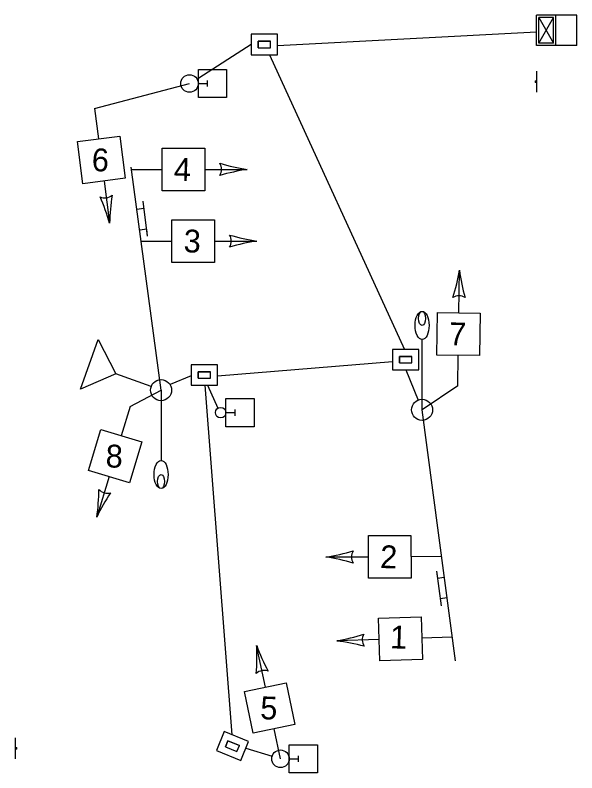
# Model space of a CAD drawing. Extents: x 995815 to 1000702, y 1981720 to 1984760.
# Drawn here: x 995815.2 to 995895.1, y 1982046.4 to 1982154.2 of the extents above; entities that cross this region are included whole.
import ezdxf

# ---------------------------------------------------------------- set-up
doc = ezdxf.new("R2010")
doc.units = 0
for name, color, linetype in [('DSN_Drain_Alignment_ArDOT_BMCD_Rt', 7, 'Continuous'), ('DSN_DRAIN_Analytics_ArDOT_BMCD_Rt', 7, 'Continuous'), ('DSN_DRAIN_Storm-Sewer_ArDOT_BMCD_Lt', 7, 'Continuous'), ('DSN_DRFT_Common-Annotations', 7, 'Continuous'), ('DSN_DRFT_Const-No-Plot', 7, 'Continuous'), ('DSN_DRFT_Guideline-No-Plot', 7, 'Continuous'), ('DSN_RDWY_Alignment', 7, 'Continuous'), ('DSN_ROW_Point-Name-Annotation', 7, 'Continuous')]:
    doc.layers.add(name, color=color, linetype=linetype)

msp = doc.modelspace()

# ---------------------------------------------------------------- linework, layer by layer
at = {"layer": 'DSN_Drain_Alignment_ArDOT_BMCD_Rt'}
for p, q in [((995824.46, 1982101), (995826.99, 1982108.06)), ((995826.99, 1982108.06), (995829.49, 1982103.18)), ((995829.49, 1982103.18), (995824.46, 1982101)), ((995834.53, 1982101.38), (995829.49, 1982103.18))]:
    msp.add_line(p, q, dxfattribs=at)
at = {"layer": 'DSN_DRAIN_Analytics_ArDOT_BMCD_Rt'}
for points in [[(995841.24, 1982146.49), (995845.24, 1982146.49), (995845.24, 1982142.49), (995841.24, 1982142.49)], [(995845.17, 1982099.68), (995849.17, 1982099.68), (995849.17, 1982095.68), (995845.17, 1982095.68)], [(995854.17, 1982050.44), (995858.17, 1982050.44), (995858.17, 1982046.44), (995854.17, 1982046.44)]]:
    msp.add_lwpolyline(points, close=True, dxfattribs=at)
at = {"layer": 'DSN_DRAIN_Storm-Sewer_ArDOT_BMCD_Lt'}
for p, q in [((995834.03, 1982122.79), (995833.37, 1982127.75)), ((995832.51, 1982126.62), (995833.5, 1982126.76)), ((995833.9, 1982123.78), (995832.91, 1982123.65)), ((995834.03, 1982122.79), (995833.9, 1982123.78)), ((995875.1, 1982075.14), (995875.23, 1982074.15)), ((995875.1, 1982075.14), (995875.76, 1982070.18)), ((995875.23, 1982074.15), (995876.22, 1982074.28)), ((995876.62, 1982071.31), (995875.63, 1982071.18))]:
    msp.add_line(p, q, dxfattribs=at)
at = {"layer": 'DSN_DRFT_Common-Annotations'}
for p, q in [((995852.49, 1982151.5), (995848.74, 1982151.5)), ((995848.74, 1982151.5), (995848.74, 1982148.58)), ((995852.49, 1982148.58), (995852.49, 1982151.5)), ((995849.74, 1982149.58), (995849.74, 1982150.5)), ((995849.74, 1982150.5), (995851.49, 1982150.5)), ((995849.74, 1982150.5), (995849.74, 1982149.58)), ((995851.49, 1982150.5), (995849.74, 1982150.5)), ((995851.49, 1982149.58), (995851.49, 1982150.5)), ((995851.49, 1982149.58), (995851.49, 1982150.5)), ((995849.74, 1982149.58), (995851.49, 1982149.58)), ((995849.74, 1982149.58), (995851.49, 1982149.58)), ((995848.74, 1982148.58), (995852.49, 1982148.58)), ((995842.56, 1982144.05), (995842.56, 1982144.92)), ((995841.24, 1982144.49), (995842.56, 1982144.49)), ((995872.61, 1982106.68), (995868.86, 1982106.68)), ((995868.86, 1982106.68), (995868.86, 1982103.76)), ((995872.61, 1982103.76), (995872.61, 1982106.68)), ((995869.86, 1982104.76), (995869.86, 1982105.68)), ((995869.86, 1982105.68), (995871.61, 1982105.68)), ((995869.86, 1982105.68), (995869.86, 1982104.76)), ((995871.61, 1982105.68), (995869.86, 1982105.68)), ((995871.61, 1982104.76), (995871.61, 1982105.68)), ((995871.61, 1982104.76), (995871.61, 1982105.68)), ((995843.98, 1982104.48), (995840.23, 1982104.48)), ((995840.23, 1982104.48), (995840.23, 1982101.56)), ((995843.98, 1982101.56), (995843.98, 1982104.48)), ((995869.86, 1982104.76), (995871.61, 1982104.76)), ((995869.86, 1982104.76), (995871.61, 1982104.76)), ((995841.23, 1982102.56), (995841.23, 1982103.48)), ((995841.23, 1982103.48), (995842.98, 1982103.48)), ((995841.23, 1982103.48), (995841.23, 1982102.56)), ((995842.98, 1982103.48), (995841.23, 1982103.48)), ((995842.98, 1982102.56), (995842.98, 1982103.48)), ((995842.98, 1982102.56), (995842.98, 1982103.48)), ((995868.86, 1982103.76), (995872.61, 1982103.76)), ((995841.23, 1982102.56), (995842.98, 1982102.56)), ((995841.23, 1982102.56), (995842.98, 1982102.56)), ((995840.23, 1982101.56), (995843.98, 1982101.56)), ((995845.17, 1982097.68), (995846.49, 1982097.68)), ((995846.49, 1982097.24), (995846.49, 1982098.12)), ((995844.91, 1982052.3), (995843.8, 1982049.6)), ((995848.37, 1982050.88), (995844.91, 1982052.3)), ((995845.1, 1982050.15), (995845.45, 1982051)), ((995845.45, 1982051), (995845.1, 1982050.15)), ((995845.1, 1982050.15), (995846.72, 1982049.48)), ((995845.1, 1982050.15), (995846.72, 1982049.48)), ((995845.45, 1982051), (995847.07, 1982050.33)), ((995847.07, 1982050.33), (995845.45, 1982051)), ((995846.72, 1982049.48), (995847.07, 1982050.33)), ((995846.72, 1982049.48), (995847.07, 1982050.33)), ((995847.26, 1982048.18), (995848.37, 1982050.88)), ((995843.8, 1982049.6), (995847.26, 1982048.18)), ((995854.17, 1982048.44), (995855.48, 1982048.44)), ((995855.48, 1982048), (995855.48, 1982048.88))]:
    msp.add_line(p, q, dxfattribs=at)
at = {"layer": 'DSN_DRFT_Const-No-Plot'}
for p, q in [((995895.07, 1982154.21), (995889.33, 1982154.21)), ((995889.33, 1982149.88), (995889.33, 1982154.21)), ((995889.66, 1982150.24), (995891.74, 1982153.88)), ((995889.66, 1982150.21), (995889.66, 1982153.88)), ((995889.66, 1982153.88), (995891.74, 1982150.21)), ((995891.74, 1982153.88), (995889.66, 1982153.88)), ((995891.74, 1982150.21), (995891.74, 1982153.88)), ((995892.07, 1982149.88), (995892.07, 1982154.21)), ((995895.07, 1982149.88), (995895.07, 1982154.21)), ((995895.07, 1982149.88), (995889.33, 1982149.88)), ((995891.74, 1982150.21), (995889.66, 1982150.21))]:
    msp.add_line(p, q, dxfattribs=at)
at = {"layer": 'DSN_DRFT_Guideline-No-Plot'}
for p, q in [((995826.47, 1982140.94), (995839.99, 1982144.49)), ((995826.47, 1982140.94), (995827.03, 1982136.62)), ((995831.73, 1982132.25), (995836.08, 1982132.25)), ((995842.14, 1982132.28), (995848.18, 1982132.28)), ((995827.84, 1982130.62), (995828.62, 1982124.63)), ((995833.12, 1982122.05), (995837.46, 1982122.05)), ((995843.53, 1982122.08), (995849.57, 1982122.08)), ((995878.28, 1982111.89), (995878.37, 1982117.93)), ((995873.06, 1982098.08), (995873.06, 1982108.08)), ((995878.14, 1982101.48), (995878.21, 1982105.83)), ((995831.54, 1982098.55), (995835.94, 1982100.87)), ((995835.94, 1982100.87), (995835.94, 1982090.87)), ((995878.14, 1982101.48), (995873.06, 1982098.08)), ((995831.54, 1982098.55), (995830.28, 1982094.39)), ((995828.55, 1982088.58), (995826.8, 1982082.8)), ((995865.43, 1982077.14), (995859.39, 1982077.13)), ((995875.84, 1982077.2), (995871.49, 1982077.18)), ((995866.95, 1982065.39), (995860.92, 1982065.2)), ((995877.36, 1982065.74), (995873.01, 1982065.6)), ((995850.77, 1982058.63), (995849.53, 1982064.54)), ((995852.92, 1982048.44), (995852.03, 1982052.7))]:
    msp.add_line(p, q, dxfattribs=at)
for points in [[(995824.04, 1982136.23), (995830.06, 1982137.02), (995830.84, 1982131.01), (995824.83, 1982130.22)], [(995836.08, 1982129.24), (995836.08, 1982135.3), (995842.14, 1982135.3), (995842.14, 1982129.24)], [(995837.46, 1982119.04), (995837.46, 1982125.1), (995843.53, 1982125.1), (995843.53, 1982119.04)], [(995881.22, 1982105.78), (995875.16, 1982105.87), (995875.26, 1982111.94), (995881.32, 1982111.84)], [(995827.39, 1982095.26), (995833.2, 1982093.51), (995831.44, 1982087.7), (995825.64, 1982089.46)], [(995871.48, 1982080.2), (995871.5, 1982074.14), (995865.43, 1982074.12), (995865.42, 1982080.18)], [(995872.92, 1982068.62), (995873.11, 1982062.56), (995867.05, 1982062.36), (995866.86, 1982068.43)], [(995854.98, 1982053.32), (995849.04, 1982052.08), (995847.81, 1982058.01), (995853.74, 1982059.25)]]:
    msp.add_lwpolyline(points, close=True, dxfattribs=at)
for centre, radius, start, end in [((995842.92, 1982132.28), 1.63, 328.1527, 31.8473), ((995852.6, 1982161.42), 29.47, 253.6536, 261.3917), ((995852.6, 1982103.13), 29.47, 98.6083, 106.3464), ((995827.94, 1982129.85), 1.63, 245.5758, 309.2704), ((995800.29, 1982116.49), 29.47, 16.0314, 23.7695), ((995858.09, 1982124.02), 29.47, 171.0766, 178.8148), ((995844.3, 1982122.08), 1.63, 328.1527, 31.8473), ((995853.98, 1982151.22), 29.47, 253.6536, 261.3917), ((995853.98, 1982092.94), 29.47, 98.6083, 106.3464), ((995849.31, 1982122.8), 29.47, 342.7499, 350.488), ((995907.58, 1982121.88), 29.47, 187.7046, 195.4427), ((995878.29, 1982112.66), 1.63, 57.249, 120.9436), ((995797.63, 1982087.01), 29.47, 351.7756, 359.5137), ((995828.32, 1982087.84), 1.63, 221.3199, 285.0146), ((995853.41, 1982070.14), 29.47, 146.8208, 154.5589), ((995854.9, 1982106.26), 29.47, 278.7585, 286.4966), ((995855.05, 1982047.98), 29.47, 73.8037, 81.5418), ((995864.65, 1982077.14), 1.63, 148.3028, 211.9975), ((995855.59, 1982094.19), 29.47, 280.4069, 288.145), ((995857.42, 1982035.93), 29.47, 75.4521, 83.1902), ((995866.18, 1982065.36), 1.63, 149.9512, 213.6459), ((995820.11, 1982062.91), 29.47, 355.4379, 3.176), ((995877.16, 1982074.81), 29.47, 200.3926, 208.1308), ((995850.61, 1982059.39), 1.63, 69.937, 133.6316)]:
    msp.add_arc(centre, radius, start, end, dxfattribs=at)
for centre, major_axis in [((995873.06, 1982110.08), (0, 2)), ((995873.06, 1982111.08), (0, -1)), ((995835.94, 1982088.87), (0, -2)), ((995835.94, 1982087.87), (0, 1))]:
    msp.add_ellipse(centre, major_axis=major_axis, ratio=0.5, dxfattribs=at)
at = {"layer": 'DSN_RDWY_Alignment'}
for p, q in [((995889.33, 1982151.78), (995852.49, 1982149.84)), ((995848.74, 1982150.04), (995841.29, 1982145.23)), ((995851.35, 1982148.58), (995870.55, 1982106.68)), ((995868.86, 1982104.89), (995843.98, 1982102.85)), ((995840.23, 1982102.89), (995837.22, 1982101.66)), ((995870.74, 1982103.76), (995872.49, 1982099.47)), ((995842.18, 1982101.56), (995846, 1982051.86)), ((995842.56, 1982101.56), (995844.03, 1982098.32)), ((995847.98, 1982049.93), (995851.72, 1982048.8))]:
    msp.add_line(p, q, dxfattribs=at)
at = {"layer": 'DSN_ROW_Point-Name-Annotation'}
for p, q in [((995889.4, 1982143.26), (995889.38, 1982146.26)), ((995889.14, 1982144.88), (995889.39, 1982144.88)), ((995889.14, 1982144.88), (995889.14, 1982144.63)), ((995889.39, 1982144.63), (995889.39, 1982144.88)), ((995889.39, 1982144.63), (995889.14, 1982144.63)), ((995835.94, 1982100.87), (995831.69, 1982132.59)), ((995877.8, 1982062.39), (995873.06, 1982098.08)), ((995815.19, 1982051.43), (995815.21, 1982048.43)), ((995815.2, 1982050.05), (995815.2, 1982049.8)), ((995815.2, 1982050.05), (995815.45, 1982050.05)), ((995815.45, 1982049.8), (995815.45, 1982050.05)), ((995815.45, 1982049.8), (995815.2, 1982049.8))]:
    msp.add_line(p, q, dxfattribs=at)
for centre, radius in [((995839.99, 1982144.49), 1.25), ((995835.94, 1982100.87), 1.5), ((995873.06, 1982098.08), 1.5), ((995844.42, 1982097.68), 0.75), ((995852.92, 1982048.44), 1.25)]:
    msp.add_circle(centre, radius, dxfattribs=at)

# ---------------------------------------------------------------- texts
at = {"layer": 'DSN_DRFT_Guideline-No-Plot'}
for s, rotation, p in [('6', 358.0939, (995826.05, 1982132.04)), ('4', 358.2498, (995837.72, 1982130.68)), ('3', 358.2498, (995839.12, 1982120.49)), ('7', 358.0939, (995876.85, 1982107.28)), ('8', 358.2498, (995828.03, 1982089.9)), ('2', 358.0939, (995867.06, 1982075.58)), ('1', 358.0939, (995868.47, 1982064.16)), ('5', 358.0939, (995850.01, 1982054.08))]:
    msp.add_text(s, height=3.25, rotation=rotation, dxfattribs=at).set_placement(p)

doc.saveas('drawing.dxf')
